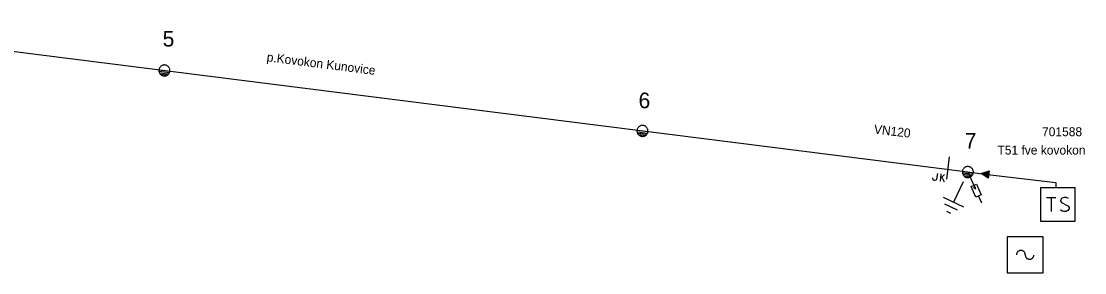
# Model space of a CAD drawing. Extents: x -540340 to -537226, y -1183949 to -1180375.
# Drawn here: x -539569.2 to -539450.7, y -1183415.1 to -1183387 of the extents above; entities that cross this region are included whole.
import ezdxf

# ---------------------------------------------------------------- set-up
doc = ezdxf.new("R2010")
doc.units = 0
for name, color, linetype in [('Vrstva 1', 7, 'Continuous'), ('Vrstva 13', 7, 'Continuous'), ('Vrstva 14', 7, 'Continuous'), ('Vrstva 15', 7, 'Continuous'), ('Vrstva 16', 7, 'Continuous'), ('Vrstva 18', 7, 'Continuous'), ('Vrstva 19', 7, 'Continuous'), ('Vrstva 2', 7, 'Continuous'), ('Vrstva 25', 7, 'Continuous'), ('Vrstva 26', 7, 'Continuous'), ('Vrstva 27', 7, 'Continuous'), ('Vrstva 34', 7, 'Continuous'), ('Vrstva 4', 7, 'Continuous'), ('Vrstva 5', 7, 'Continuous'), ('Vrstva 59', 7, 'Continuous'), ('Vrstva 6', 7, 'Continuous'), ('Vrstva 7', 7, 'Continuous')]:
    doc.layers.add(name, color=color, linetype=linetype)

# ---------------------------------------------------------------- blocks, each defined once
blk = doc.blocks.new('VN840')
at = {"layer": 'Vrstva 15'}
for points in [[(-0.01, 1.41), (-0.01, -1.09)], [(-1.51, -1.24), (-1.51, -1.15)], [(-1.09, -0.59), (-1.09, -1.24)], [(-0.68, -0.59), (-0.68, -1.42)], [(-0.68, -1.11), (-0.27, -0.59)], [(-0.54, -0.94), (-0.2, -1.42)], [(-1.48, -1.35), (-1.51, -1.24)], [(-1.33, -1.42), (-1.48, -1.35)], [(-1.27, -1.42), (-1.33, -1.42)], [(-1.13, -1.35), (-1.27, -1.42)], [(-1.09, -1.24), (-1.13, -1.35)]]:
    blk.add_lwpolyline(points, dxfattribs=at)
blk = doc.blocks.new('VN440')
at = {"layer": 'Vrstva 2'}
for points in [[(1.22, 0), (1.21, 0.13), (1.19, 0.25), (1.16, 0.38), (1.11, 0.5), (1.05, 0.61), (0.98, 0.72), (0.9, 0.82), (0.81, 0.91), (0.71, 0.99), (0.6, 1.06), (0.49, 1.12), (0.37, 1.16), (0.25, 1.2), (0.12, 1.22), (-0.01, 1.22), (-0.14, 1.22), (-0.26, 1.2), (-0.39, 1.16), (-0.51, 1.12), (-0.62, 1.06), (-0.73, 0.99), (-0.83, 0.91), (-0.92, 0.82), (-1, 0.72), (-1.07, 0.61), (-1.13, 0.5), (-1.18, 0.38), (-1.21, 0.25), (-1.23, 0.13), (-1.24, 0), (-1.23, -0.13), (-1.21, -0.26), (-1.18, -0.38), (-1.13, -0.5), (-1.07, -0.62), (-1, -0.73), (-0.92, -0.83), (-0.83, -0.92), (-0.73, -1), (-0.62, -1.07), (-0.51, -1.13), (-0.39, -1.17), (-0.26, -1.2), (-0.14, -1.23), (-0.01, -1.23), (0.12, -1.23), (0.25, -1.2), (0.37, -1.17), (0.49, -1.13), (0.6, -1.07), (0.71, -1), (0.81, -0.92), (0.9, -0.83), (0.98, -0.73), (1.05, -0.62), (1.11, -0.5), (1.16, -0.38), (1.19, -0.26), (1.21, -0.13), (1.22, 0)], [(-1.24, 0), (1.22, 0)], [(-1.18, -0.34), (1.1, -0.34)], [(-1.01, -0.63), (0.97, -0.63)], [(-0.74, -0.92), (0.68, -0.92)]]:
    blk.add_lwpolyline(points, dxfattribs=at)
blk = doc.blocks.new('VN890')
at = {"layer": 'Vrstva 4'}
for points in [[(-0.41, 0.41), (0.41, 0)], [(-0.41, -0.41), (-0.41, 0.41)], [(0.41, 0), (-0.41, -0.41)], [(-0.34, 0.31), (0.27, 0), (-0.34, -0.3), (-0.34, 0.31)], [(-0.26, 0.2), (0.1, 0), (-0.26, -0.18), (-0.26, 0.2)], [(-0.19, 0.09), (-0.04, 0), (-0.19, -0.08), (-0.19, 0.09)], [(-0.16, -0.01), (-0.16, 0.03), (-0.13, 0.01), (-0.16, -0.01)]]:
    blk.add_lwpolyline(points, dxfattribs=at)
blk = doc.blocks.new('VN820')
at = {"layer": 'Vrstva 13'}
for points in [[(0, 0), (0, -2.1)], [(-0.32, -1.63), (0.34, -1.63)], [(-0.32, -2.95), (-0.32, -1.63)], [(0, -2.1), (-0.12, -1.86)], [(0, -2.1), (0.12, -1.86)], [(0.34, -1.63), (0.34, -2.95)], [(0.34, -2.95), (-0.32, -2.95)], [(0, -2.95), (0, -3.75)]]:
    blk.add_lwpolyline(points, dxfattribs=at)
blk = doc.blocks.new('VN810')
at = {"layer": 'Vrstva 14'}
for points in [[(0, -1.25), (0, -3.75)], [(1.25, -3.75), (-1.25, -3.75)], [(0.77, -4.37), (-0.8, -4.37)], [(0, -5), (-0.25, -5)], [(0.27, -5), (0, -5)]]:
    blk.add_lwpolyline(points, dxfattribs=at)
blk = doc.blocks.new('VN740')
at = {"layer": 'Vrstva 1'}
for points in [[(2, 2), (-2, 2)], [(-2, 2), (-2, -2)], [(2, -2), (2, 2)], [(0, 0), (0, 0.05), (-0.01, 0.1), (-0.02, 0.15), (-0.04, 0.2), (-0.06, 0.24), (-0.09, 0.29), (-0.12, 0.33), (-0.16, 0.36), (-0.2, 0.4), (-0.24, 0.42), (-0.29, 0.45), (-0.34, 0.47), (-0.38, 0.48), (-0.44, 0.49), (-0.49, 0.49), (-0.54, 0.49), (-0.59, 0.48), (-0.64, 0.47), (-0.69, 0.45), (-0.73, 0.43), (-0.77, 0.4), (-0.81, 0.37), (-0.85, 0.33), (-0.88, 0.29), (-0.91, 0.25), (-0.93, 0.2), (-0.95, 0.16), (-0.97, 0.11), (-0.97, 0.06), (-0.98, 0), (-0.98, 0)], [(0, 0), (0, -0.05), (0.01, -0.1), (0.02, -0.15), (0.04, -0.2), (0.06, -0.24), (0.09, -0.28), (0.12, -0.32), (0.15, -0.36), (0.19, -0.39), (0.23, -0.42), (0.28, -0.44), (0.32, -0.46), (0.37, -0.48), (0.42, -0.49), (0.47, -0.49), (0.52, -0.49), (0.57, -0.48), (0.62, -0.47), (0.67, -0.45), (0.71, -0.43), (0.75, -0.4), (0.79, -0.37), (0.83, -0.34), (0.86, -0.3), (0.89, -0.26), (0.91, -0.21), (0.93, -0.17), (0.95, -0.12), (0.96, -0.07), (0.96, -0.02), (0.96, -0.02)], [(-2, -2), (2, -2)]]:
    blk.add_lwpolyline(points, dxfattribs=at)
blk = doc.blocks.new('VN640')
at = {"layer": 'Vrstva 6'}
for points in [[(-1.89, 1.89), (1.89, 1.89)], [(-1.89, -1.89), (-1.89, 1.89)], [(1.89, 1.89), (1.89, -1.89)], [(-1.26, 0.79), (-0.22, 0.79)], [(-0.73, 0.79), (-0.73, -0.79)], [(1.2, 0.66), (0.94, 0.79), (0.66, 0.79), (0.41, 0.66), (0.28, 0.47), (0.28, 0.41), (0.41, 0.22), (1.13, -0.16), (1.26, -0.32), (1.26, -0.47), (1.13, -0.66), (0.91, -0.79), (0.63, -0.79), (0.5, -0.73), (0.28, -0.6)], [(1.89, -1.89), (-1.89, -1.89)]]:
    blk.add_lwpolyline(points, dxfattribs=at)

msp = doc.modelspace()

# ---------------------------------------------------------------- linework, layer by layer
at = {"layer": 'Vrstva 4'}
msp.add_lwpolyline([(-539596.71, -1183386.99), (-539463.72, -1183403.82)], dxfattribs=at)
at = {"layer": 'Vrstva 5'}
msp.add_lwpolyline([(-539463.72, -1183403.82), (-539461.82, -1183404.05), (-539453.94, -1183405), (-539453.94, -1183405.57)], dxfattribs=at)

# ---------------------------------------------------------------- block references
at = {"layer": 'Vrstva 13', "xscale": 0.5}
for p, yscale, rotation in [((-539553.23, -1183392.49), 0.5, -7.2147722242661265), ((-539499.97, -1183399.24), 0.5000000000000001, -7.214772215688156), ((-539463.72, -1183403.83), 0.49999999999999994, -7.214772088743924)]:
    msp.add_blockref('VN440', p, dxfattribs=dict(at, yscale=yscale, rotation=rotation))
at = {"layer": 'Vrstva 15', "rotation": -25.225933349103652}
msp.add_blockref('VN810', (-539463.72, -1183403.81), dxfattribs=at)
at = {"layer": 'Vrstva 16', "rotation": 23.530427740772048}
msp.add_blockref('VN820', (-539463.72, -1183403.82), dxfattribs=at)
at = {"layer": 'Vrstva 18', "rotation": -7.2147722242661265}
msp.add_blockref('VN840', (-539465.97, -1183403.54), dxfattribs=at)
at = {"layer": 'Vrstva 19', "rotation": 173.17732764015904}
msp.add_blockref('VN890', (-539461.82, -1183404.05), dxfattribs=at)
at = {"layer": 'Vrstva 25'}
msp.add_blockref('VN640', (-539453.7, -1183407.46), dxfattribs=at)
at = {"layer": 'Vrstva 34'}
msp.add_blockref('VN740', (-539457.33, -1183413.08), dxfattribs=at)

# ---------------------------------------------------------------- texts
at = {"layer": 'Vrstva 14'}
for s, p in [('5', (-539553.43, -1183389.82)), ('6', (-539500.41, -1183396.71)), ('7', (-539464.07, -1183401.21))]:
    msp.add_text(s, height=1.75, dxfattribs=at).set_placement(p)
at = {"layer": 'Vrstva 26'}
msp.add_text('701588', height=1, dxfattribs=at).set_placement((-539455.46, -1183399.83))
at = {"layer": 'Vrstva 27'}
msp.add_text('T51 fve kovokon', height=1, dxfattribs=at).set_placement((-539460.43, -1183401.88))
at = {"layer": 'Vrstva 59'}
msp.add_text('p.Kovokon Kunovice', height=1, rotation=352.785, dxfattribs=at).set_placement((-539541.88, -1183391.46))
at = {"layer": 'Vrstva 7'}
msp.add_text('VN120', height=1, rotation=353.178, dxfattribs=at).set_placement((-539474.23, -1183399.52))

doc.saveas('drawing.dxf')
